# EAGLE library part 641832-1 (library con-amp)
Universal MATE-N-LOK .250" Centerline, 600 V, 19 - 36 A max Source: http://catalog.tycoelectronics.com/ .. ENG_CD_641832_L.pdf
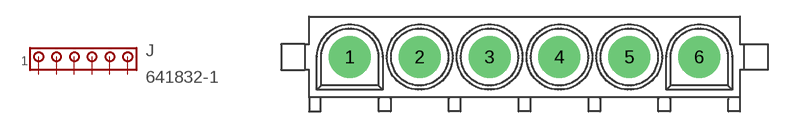
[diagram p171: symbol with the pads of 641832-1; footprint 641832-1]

Designator prefix J

## 641832-1 (MF: TYCO ELECTRONICS; MPN: 641832-1; OC_FARNELL: 1821271; OC_NEWARK: 90F4389)  [641832-1]
1  1  pas
2  2  pas
3  3  pas
4  4  pas
5  5  pas
6  6  pas

## Footprint 641832-1 (pad centres in mm)
Universal MATE-N-LOK .250" Centerline, 600 V, 19 - 36 A max Source: http://catalog.tycoelectronics.com/ .. ENG_CD_641832_L.pdf
drill 1.8 pad 3.81 round: 1 -15.875,0; 2 -9.525,0; 3 -3.175,0; 4 3.175,0; 5 9.525,0; 6 15.875,0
